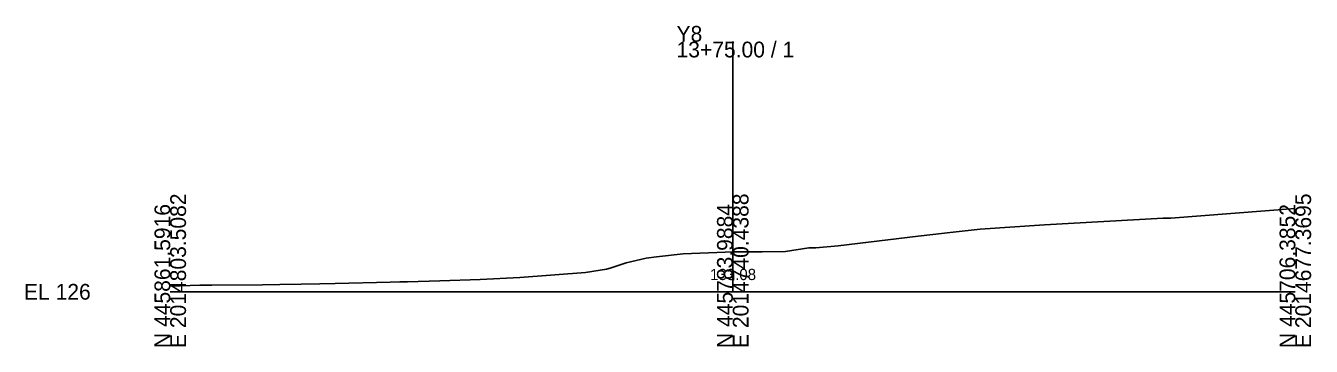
# Model space of a CAD drawing. Extents: x -26 to 1403, y -10 to 8043.
# Drawn here: x -25.7 to 202.8, y 7490.3 to 7547.3 of the extents above; entities that cross this region are included whole.
import ezdxf

# ---------------------------------------------------------------- set-up
doc = ezdxf.new("R2010")
doc.units = 0
for name, color, linetype in [('Default', 7, 'Continuous'), ('Exist Cross Section Cell', 7, 'Continuous'), ('Exist XS Center Line Elevation Label', 7, 'Continuous'), ('Exist XS Ground Line', 7, 'Continuous')]:
    doc.layers.add(name, color=color, linetype=linetype)

msp = doc.modelspace()

# ---------------------------------------------------------------- linework, layer by layer
at = {"layer": 'Exist Cross Section Cell'}
for p, q in [((100, 7500), (100, 7544.48)), ((0, 7500), (100, 7500)), ((100, 7500), (200, 7500))]:
    msp.add_line(p, q, dxfattribs=at)
at = {"layer": 'Exist XS Ground Line'}
msp.add_lwpolyline([(0, 7500.99), (3.53, 7501.12), (5.26, 7501.2), (7.39, 7501.2), (16.41, 7501.22), (19.48, 7501.3), (23.25, 7501.34), (26.59, 7501.39), (29.3, 7501.46), (39.11, 7501.72), (40.81, 7501.76), (42.19, 7501.77), (47.92, 7501.96), (55.08, 7502.18), (62.14, 7502.54), (73.83, 7503.45), (77.53, 7504.01), (78.23, 7504.18), (81.04, 7505.16), (84.61, 7505.96), (86.44, 7506.22), (91.19, 7506.74), (98.65, 7507.03), (100, 7507.08), (101, 7507.12), (105.2, 7507.1), (109.36, 7507.15), (113.54, 7507.83), (114.74, 7507.81), (118.76, 7508.2), (132.97, 7509.88), (137.61, 7510.44), (138.11, 7510.46), (143.95, 7511.15), (155.42, 7511.9), (176.5, 7513.1), (177.89, 7513.1), (200, 7514.83)], dxfattribs=at)

# ---------------------------------------------------------------- texts
at = {"layer": 'Default'}
msp.add_text('-', height=0.0001, dxfattribs=at).set_placement((0, 7500))
at = {"layer": 'Exist Cross Section Cell'}
for s, p in [('Y8', (90, 7544.48)), ('13+75.00 / 1', (90, 7541.68)), ('EL 126', (-26, 7498.6))]:
    msp.add_text(s, height=2.8, dxfattribs=at).set_placement(p)
for s, p in [('E 2014803.5082', (2.8, 7490)), ('E 2014740.4388', (102.8, 7490)), ('E 2014677.3695', (202.8, 7490)), ('N 445861.5916', (0, 7490)), ('N 445783.9884', (100, 7490)), ('N 445706.3852', (200, 7490))]:
    msp.add_text(s, height=2.8, rotation=90, dxfattribs=at).set_placement(p)
at = {"layer": 'Exist XS Center Line Elevation Label'}
msp.add_text('133.08', height=2, dxfattribs=at).set_placement((95.96, 7502.08))

doc.saveas('drawing.dxf')
